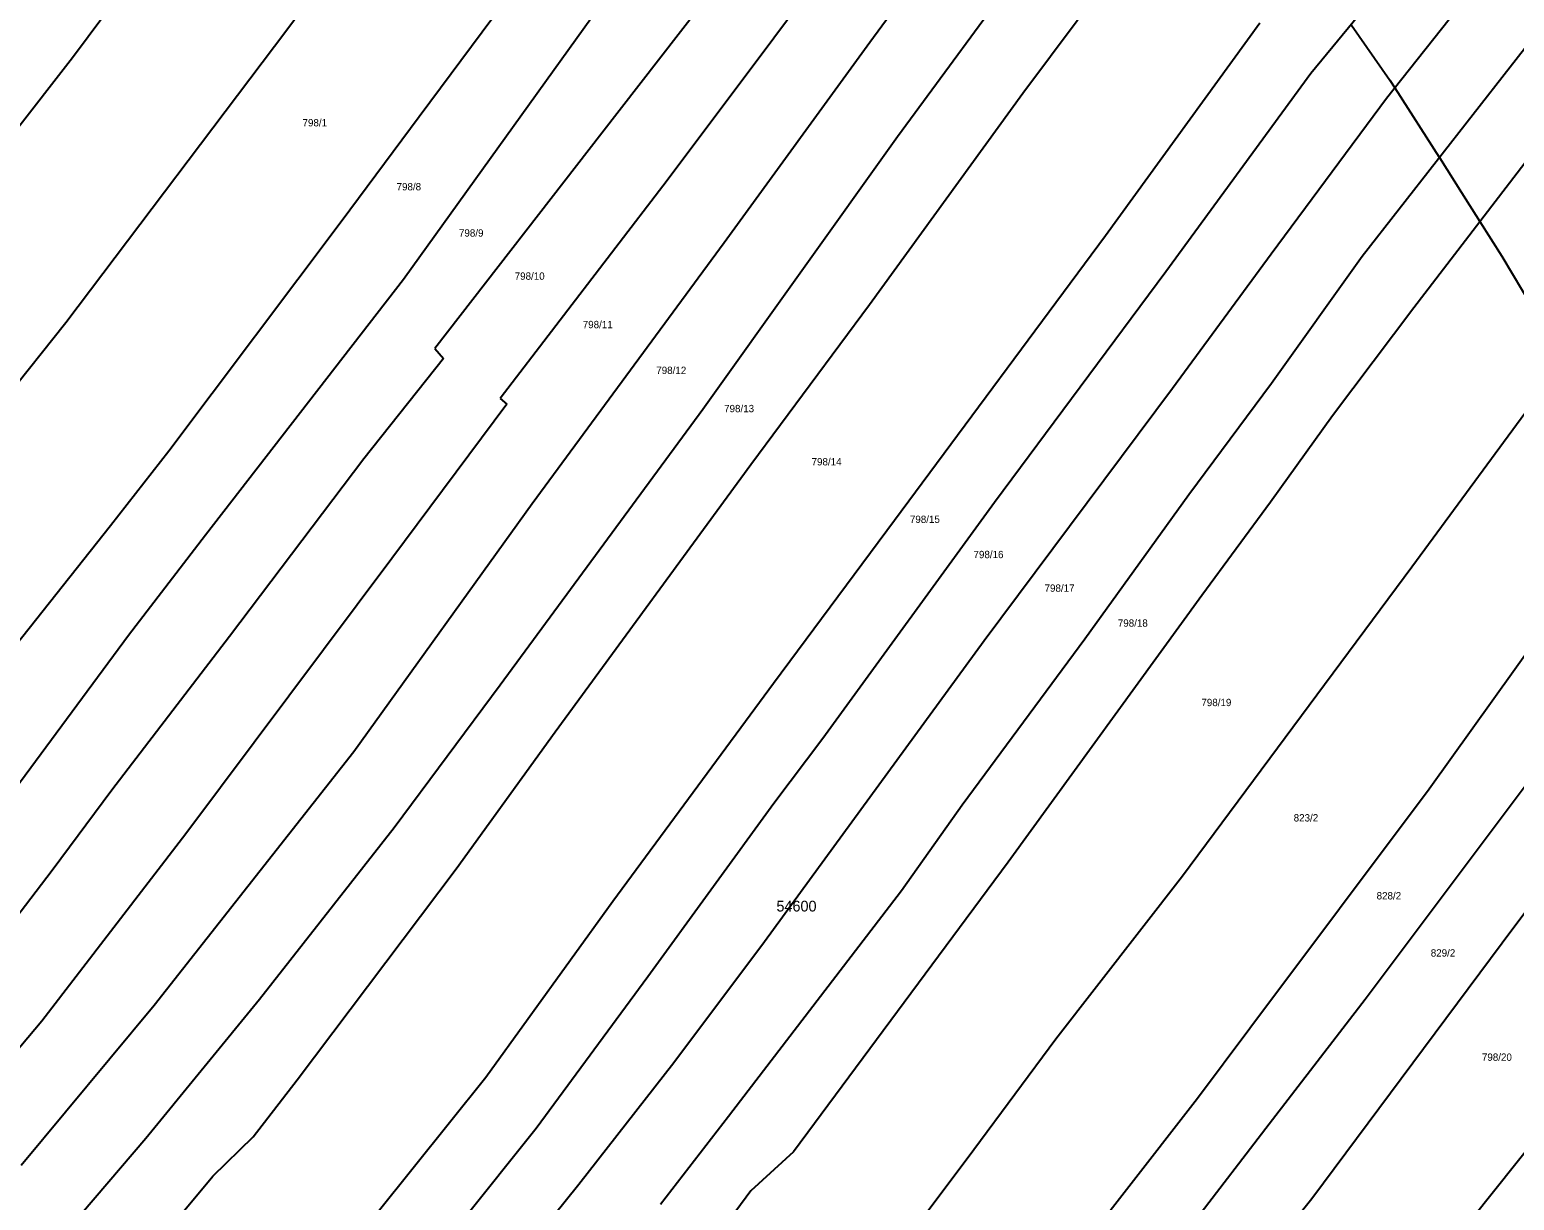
# Model space of a CAD drawing. Extents: x -749173 to -746119, y -1132678 to -1130338.
# Drawn here: x -747979.1 to -747634.7, y -1131595.4 to -1131323.7 of the extents above; entities that cross this region are included whole.
import ezdxf

# ---------------------------------------------------------------- set-up
doc = ezdxf.new("R2010")
doc.units = 0
for name, color, linetype in [('Vrstva 18', 7, 'Continuous'), ('Vrstva 52', 7, 'Continuous'), ('Vrstva 53', 7, 'Continuous'), ('Vrstva 6', 7, 'Continuous')]:
    doc.layers.add(name, color=color, linetype=linetype)

msp = doc.modelspace()

# ---------------------------------------------------------------- linework, layer by layer
at = {"layer": 'Vrstva 52'}
msp.add_lwpolyline([(-747672.44, -1131322.62), (-747663.5, -1131335.37), (-747662.34, -1131337.18), (-747652.06, -1131353.25), (-747652.02, -1131353.31), (-747646.88, -1131361.46), (-747642.64, -1131368.2), (-747637.56, -1131376.25), (-747623.14, -1131400.37)], dxfattribs=at)
at = {"layer": 'Vrstva 6'}
for points in [[(-747919.45, -1131323.71), (-747870.95, -1131258.84)], [(-747748.68, -1131338.4), (-747710.63, -1131287.46)], [(-747939.35, -1131290.2), (-747969.15, -1131330.2)], [(-747781.73, -1131292.56), (-747831.18, -1131358.67)], [(-747784.2, -1131326.61), (-747760.62, -1131294.4)], [(-747857, -1131301.23), (-747888.73, -1131343.94)], [(-747681.87, -1131333.76), (-747656, -1131302.39)], [(-747814.92, -1131307.18), (-747846.34, -1131347.72)], [(-747747.86, -1131307.75), (-747777.73, -1131348.55)], [(-747646.2, -1131316.75), (-747664.28, -1131339.63)], [(-747892.39, -1131381.59), (-747846.71, -1131318.11)], [(-747970.67, -1131391.64), (-747919.45, -1131323.71)], [(-747693.71, -1131322.2), (-747729.49, -1131371.5)], [(-747669.96, -1131376.28), (-747627.04, -1131321.32)], [(-747817.95, -1131373.1), (-747784.2, -1131326.61)], [(-747969.15, -1131330.2), (-748010.54, -1131383.33)], [(-747715.49, -1131379.82), (-747681.87, -1131333.76)], [(-747784.23, -1131387.47), (-747748.68, -1131338.4)], [(-747664.28, -1131339.63), (-747691.09, -1131375.78)], [(-747620.26, -1131339), (-747658, -1131388.25)], [(-747888.73, -1131343.94), (-747906.82, -1131368.28)], [(-747846.34, -1131347.72), (-747885.07, -1131397.67)], [(-747777.73, -1131348.55), (-747822.94, -1131411.83)], [(-747831.18, -1131358.67), (-747869.95, -1131409.28)], [(-747906.82, -1131368.28), (-747946.8, -1131421.49)], [(-747729.49, -1131371.5), (-747778.43, -1131437.61)], [(-747862.5, -1131433.61), (-747817.95, -1131373.1)], [(-747691.09, -1131375.78), (-747713.97, -1131406.96)], [(-747690.98, -1131405.7), (-747669.96, -1131376.28)], [(-747938.32, -1131440.9), (-747892.39, -1131381.59)], [(-747755.24, -1131433.32), (-747715.49, -1131379.82)], [(-747811.82, -1131424.61), (-747784.23, -1131387.47)], [(-747658, -1131388.25), (-747676.82, -1131413.33)], [(-747658.45, -1131448.35), (-747613.7, -1131387.55)], [(-747999.11, -1131427.19), (-747970.67, -1131391.64)], [(-747885.07, -1131397.67), (-747883.06, -1131399.99)], [(-747883.06, -1131399.99), (-747901.57, -1131423.28)], [(-747710.2, -1131431.58), (-747690.98, -1131405.7)], [(-747869.95, -1131409.28), (-747868.39, -1131410.63)], [(-747713.97, -1131406.96), (-747757.65, -1131465.52)], [(-747868.39, -1131410.63), (-747895.09, -1131446.4)], [(-747822.94, -1131411.83), (-747869.95, -1131475.83)], [(-747676.82, -1131413.33), (-747691.23, -1131433.37)], [(-747946.8, -1131421.49), (-747960.37, -1131438.84)], [(-747901.57, -1131423.28), (-747932.73, -1131464.51)], [(-747857.18, -1131486.6), (-747811.82, -1131424.61)], [(-747903.91, -1131491.23), (-747862.5, -1131433.61)], [(-747795.07, -1131488.14), (-747755.24, -1131433.32)], [(-747734.31, -1131465.05), (-747710.2, -1131431.58)], [(-747691.23, -1131433.37), (-747707.12, -1131455.02)], [(-747960.37, -1131438.84), (-748001.42, -1131490.57)], [(-747956.18, -1131464.19), (-747938.32, -1131440.9)], [(-747778.43, -1131437.61), (-747806.53, -1131475.44)], [(-747614.66, -1131444.39), (-747654.43, -1131499.96)], [(-747895.09, -1131446.4), (-747942.87, -1131510.32)], [(-747711.67, -1131520.04), (-747658.45, -1131448.35)], [(-747707.12, -1131455.02), (-747752.07, -1131516.87)], [(-747986.12, -1131504.66), (-747956.18, -1131464.19)], [(-747932.73, -1131464.51), (-747960.03, -1131500.15)], [(-747762.78, -1131503.59), (-747734.31, -1131465.05)], [(-747757.65, -1131465.52), (-747808.64, -1131535.34)], [(-747806.53, -1131475.44), (-747843.82, -1131525.97)], [(-747869.95, -1131475.83), (-747894.55, -1131508.92)], [(-747637.49, -1131535.62), (-747596.53, -1131480.99)], [(-747880.11, -1131518.39), (-747857.18, -1131486.6)], [(-747806.42, -1131503.18), (-747795.07, -1131488.14)], [(-747950.23, -1131550.08), (-747903.91, -1131491.23)], [(-747669.23, -1131548.64), (-747625.65, -1131490.48)], [(-747960.03, -1131500.15), (-747973.86, -1131518.8)], [(-747654.43, -1131499.96), (-747696.05, -1131555.49)], [(-747835.67, -1131543.4), (-747806.42, -1131503.18)], [(-747776.82, -1131523.47), (-747762.78, -1131503.59)], [(-747894.55, -1131508.92), (-747925.8, -1131548.77)], [(-747942.87, -1131510.32), (-747976.31, -1131553.75)], [(-747973.86, -1131518.8), (-748001.95, -1131555.56)], [(-747917.02, -1131567.38), (-747880.11, -1131518.39)], [(-747752.07, -1131516.87), (-747801.87, -1131584.09)], [(-747741.05, -1131557.9), (-747711.67, -1131520.04)], [(-747816.97, -1131575.83), (-747776.82, -1131523.47)], [(-747843.82, -1131525.97), (-747873.23, -1131566.86)], [(-747808.64, -1131535.34), (-747829.65, -1131563.42)], [(-747681.61, -1131594.97), (-747637.49, -1131535.62)], [(-747861.58, -1131578.6), (-747835.67, -1131543.4)], [(-747981.03, -1131587.21), (-747950.23, -1131550.08)], [(-747925.8, -1131548.77), (-747952.16, -1131580.99)], [(-747691.54, -1131577.63), (-747669.23, -1131548.64)], [(-747976.31, -1131553.75), (-748006.35, -1131589.51)], [(-747760.08, -1131583.56), (-747741.05, -1131557.9)], [(-747696.05, -1131555.49), (-747708.15, -1131571.7)], [(-747829.65, -1131563.42), (-747851.66, -1131591.69)], [(-747927.22, -1131580.6), (-747917.02, -1131567.38)], [(-747873.23, -1131566.86), (-747915.42, -1131619.45)], [(-747708.15, -1131571.7), (-747742.69, -1131616.2)], [(-747895.76, -1131621.42), (-747861.58, -1131578.6)], [(-747832.75, -1131596.26), (-747816.97, -1131575.83)], [(-747709.1, -1131600.51), (-747691.54, -1131577.63)], [(-747952.16, -1131580.99), (-747972.95, -1131605.36)], [(-747936.63, -1131589.74), (-747927.22, -1131580.6)], [(-747629.09, -1131580.38), (-747664.74, -1131625.11)], [(-747801.87, -1131584.09), (-747811.79, -1131593.14)], [(-747806.67, -1131645.86), (-747760.08, -1131583.56)], [(-747953.56, -1131610.11), (-747936.63, -1131589.74)], [(-747851.66, -1131591.69), (-747879, -1131625.66)], [(-747811.79, -1131593.14), (-747842.01, -1131634.16)], [(-747707.2, -1131626.86), (-747681.61, -1131594.97)]]:
    msp.add_lwpolyline(points, dxfattribs=at)

# ---------------------------------------------------------------- texts
at = {"layer": 'Vrstva 18'}
for s, p in [('798/1', (-747915.79, -1131346.13)), ('798/8', (-747893.97, -1131360.98)), ('798/9', (-747879.5, -1131371.71)), ('798/10', (-747866.57, -1131381.72)), ('798/11', (-747850.78, -1131392.96)), ('798/12', (-747833.72, -1131403.59)), ('798/13', (-747817.98, -1131412.46)), ('798/14', (-747797.69, -1131424.81)), ('798/15', (-747774.88, -1131438.16)), ('798/16', (-747760.12, -1131446.33)), ('798/17', (-747743.64, -1131454.13)), ('798/18', (-747726.64, -1131462.24)), ('798/19', (-747707.25, -1131480.67)), ('823/2', (-747685.84, -1131507.44)), ('828/2', (-747666.6, -1131525.53)), ('829/2', (-747654.04, -1131538.79)), ('798/20', (-747642.17, -1131562.98))]:
    msp.add_text(s, height=1.7, dxfattribs=at).set_placement(p)
at = {"layer": 'Vrstva 53'}
msp.add_text('54600', height=2.5, dxfattribs=at).set_placement((-747805.84, -1131528.33))

doc.saveas('drawing.dxf')
